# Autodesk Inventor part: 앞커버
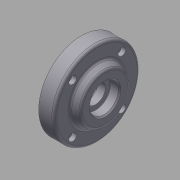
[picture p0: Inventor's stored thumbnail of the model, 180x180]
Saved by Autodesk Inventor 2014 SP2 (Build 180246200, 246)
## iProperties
Company: 한국ATC센터
Created: 2015-12
Part Number: 앞커버
Document SubType Name: Modeling
Designer: 앞커버
Density: 2.71 g/cm^3
Mass: 114.339 g
Surface Area: 117.889 cm^2
Volume: 42.1916 cm^3
Material: 알루미늄 6061
Appearance: 알루미늄 - 평지
Author: mdu
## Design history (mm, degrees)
sketch "스케치1"
  geometry: L1 (-11.5, 0)-(11.5, 0); L2 (11.5, 0)-(11.5, 22.5); L3 (11.5, 22.5)-(6.5, 22.5); L4 (6.5, 22.5)-(6.5, 32.5); L5 (6.5, 32.5)-(-5.5, 32.5); L6 (-5.5, 32.5)-(-5.5, 21); L7 (-5.5, 21)-(-11.5, 18.202); L8 (-11.5, 18.202)-(-11.5, 0); 2 further points
  constraints: 16 end point, 3 parallel, 3 perpendicular, 1 coincident, 1 horizontal, 1 midpoint
  dimensions: "d0" = 23 distance of L1.start L1.end; "d1" = 65 diameter of L5 L1; "d2" = 45 diameter of L3 L1; "d3" = 42 diameter of L6.end L1; "d4" = 115 deg angle of L7 L6; "d5" = 12 distance of L4.end L5.end; "d6" = 5 distance of L2.end L3.end
revolve "회전1" sketch "스케치1" stored, may be unused: angle "d7" = 90 deg
sketch "스케치2"
  geometry: L1 (0, 0)-(32.5, 0); L2 (0, 0)-(18.738, 18.738); 1 further point
  constraints: 4 end point, 1 horizontal, 1 horizontal alignment, 1 other
  dimensions: "d8" = 45 deg angle of L1 L2; "d9" = 26.5 distance of L1.start L2.end
hole "구멍1" sketch "스케치2" at (18.738, 18.738) diameter "d10" = 3.4; stored, may be unused: countersink angle "d14" = 90 deg, drill point angle "d16" = 118 deg; dims "d11" = 6, "d12" = 6, "d13" = 3.3, "d15" = 8
fillet "모깎기1" dims "d20" = 2
hole "구멍2" diameter "d23" = 15; stored, may be unused: countersink angle "d27" = 90 deg, drill point angle "d29" = 118 deg; dims "d21" = 10, "d22" = 10, "d24" = 6, "d25" = 32, "d26" = 10, "d28" = 8
hole "구멍3" diameter "d32" = 22; stored, may be unused: countersink angle "d36" = 90 deg, drill point angle "d38" = 0 deg; dims "d30" = 10, "d31" = 10, "d33" = 6, "d34" = 32, "d35" = 10, "d37" = 7.3
chamfer "모따기1" distance "d39" = 1; stored, may be unused: second distance "d40" = 2, angle "d41" = 45 deg
fillet "모깎기2" dims "d42" = 0.3
node "솔리드1"
pattern_circular "원형 패턴1" dims angle "d18" = 360 deg
